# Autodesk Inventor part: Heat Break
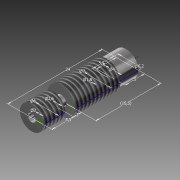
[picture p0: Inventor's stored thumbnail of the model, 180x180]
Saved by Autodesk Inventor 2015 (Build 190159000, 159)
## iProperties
Created: 2015-02
Part Number: Heat Break
Material: Типовые
Document SubType Name: Modeling
Designer: Parabolik
Density: 1 g/cm^3
Appearance: По умолчанию
Author: Parabolik
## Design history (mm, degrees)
sketch "Эскиз1"
  geometry: L1 (0, 0)-(0, 27); L2 (1, 0)-(3, 0); L3 (3, 0)-(3, 5.5); L4 (3, 5.5)-(1.3, 5.5); L5 (1.3, 5.5)-(1.3, 7.5); L6 (1.3, 7.5)-(3.5, 7.5); L7 (3.5, 7.5)-(3.5, 19); L8 (3.1, 24)-(2, 24); L9 (0.9, 18.5)-(0.9, 7.5); L10 (1, 0)-(1, 5.5); L11 (0.9, 7.5)-(1, 5.5); L12 (2, 24)-(2, 19); L13 (2, 19)-(0.9, 18.5); L14 (3.1, 24)-(3.1, 19); L15 (3.1, 19)-(3.5, 19)
  constraints: 30 end point, 7 perpendicular, 4 vertical, 1 horizontal, 1 parallel
  dimensions: "d3" = 2 distance of L4.end L5.end; "d4" = 7 diameter of L7 L1; "d5" = 24 distance between parallel lines of L8 L2; "d6" = 2.6 diameter of L5 L1; "d7" = 6 diameter of L3 L1; "d10" = 1.8 diameter of L9 L1; "d12" = 2 diameter of L10 L1; "d13" = 5.5 distance from line of L9.start L8; "d14" = 5 distance of L8.end L12.end; "d15" = 4 diameter of L12 L1; "d16" = 5.5 distance between parallel lines of L4 L2; "d30" = 16.5 distance between parallel lines of L8 L6 (derived); "d58" = 5 distance of L8.start L14.end; "d59" = 6.2 diameter of L14 L1
revolve "Вращение1" stored, may be unused: angle "d18" = 90 deg
feature "Резьба1" dims "d19" = 10, "d20" = 0
feature "Резьба2" dims "d21" = 11.5, "d22" = 0
node "Твердое тело1"
